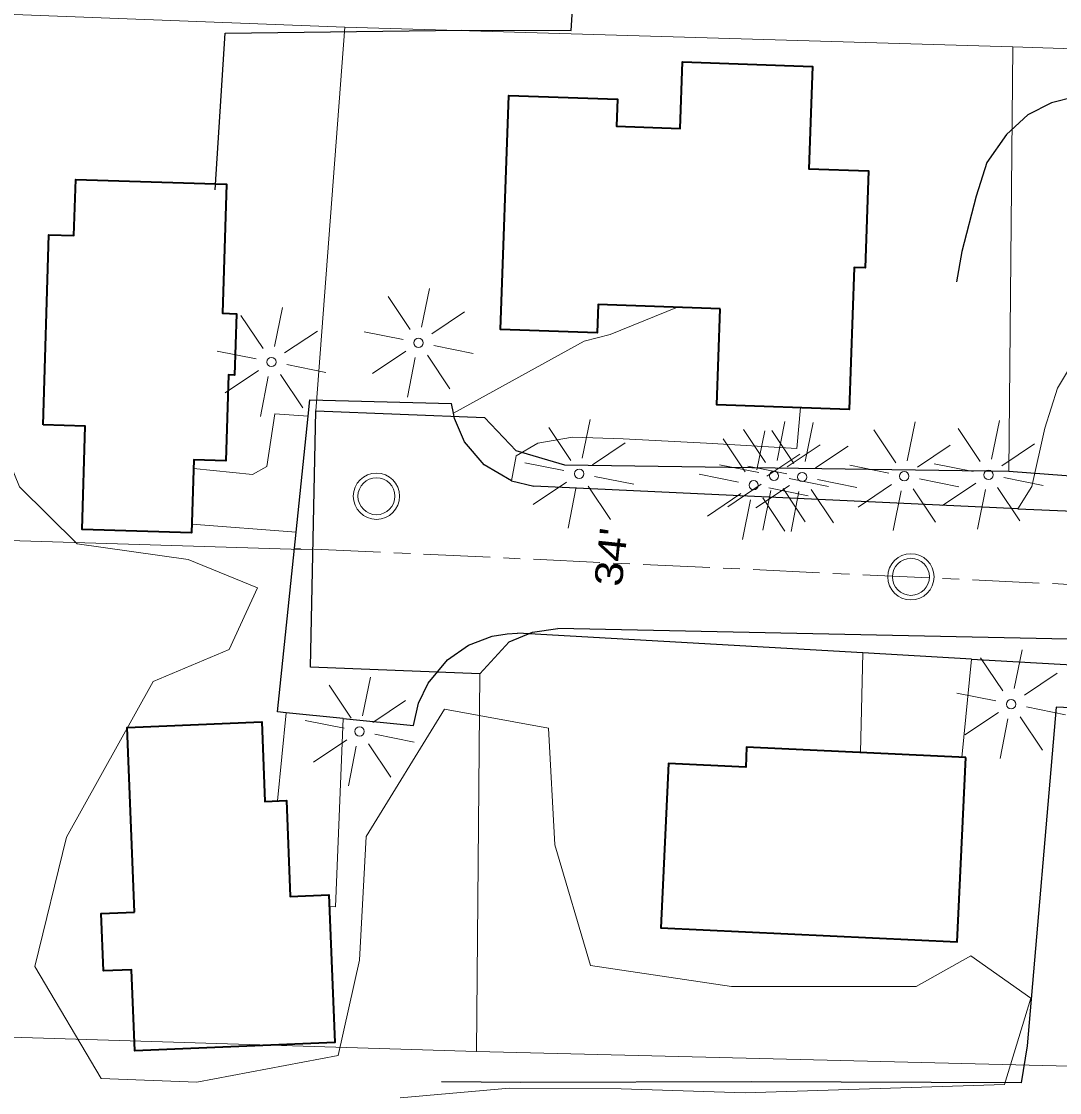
# Model space of a CAD drawing. Extents: x -861682 to -858969, y -1797841 to -1795153.
# Drawn here: x -859366.1 to -859141.7, y -1797575.9 to -1797344.4 of the extents above; entities that cross this region are included whole.
import ezdxf

# ---------------------------------------------------------------- set-up
doc = ezdxf.new("R2010")
doc.units = 0
doc.header["$LTSCALE"] = 2.4
doc.linetypes.add('LONG_DASH_SHORT_DASH', pattern=[9.9, 6, -1.2, 1.5, -1.2])
for name, color, linetype, lineweight in [('10', 7, 'Continuous', 25), ('11', 7, 'Continuous', 13), ('12', 7, 'Continuous', 35), ('14', 7, 'Continuous', 25), ('17', 7, 'Continuous', 13), ('18', 7, 'Continuous', 13), ('30', 7, 'Continuous', 13), ('32', 7, 'LONG_DASH_SHORT_DASH', 13), ('36', 7, 'Continuous', 13), ('42', 7, 'Continuous', 25)]:
    doc.layers.add(name, color=color, linetype=linetype, lineweight=lineweight)
doc.layers.add('43', color=7, linetype='Continuous')

msp = doc.modelspace()

# ---------------------------------------------------------------- linework, layer by layer
at = {"layer": '10'}
for p, q in [((-859272.713, -1797429.031), (-859273.117, -1797426.947)), ((-859260.141, -1797443.689), (-859255.295, -1797444.87)), ((-859150.644, -1797449.718), (-859255.295, -1797444.87)), ((-859150.644, -1797449.718), (-859138.672, -1797450.273)), ((-859184.173, -1797480.878), (-859258.846, -1797476.64)), ((-859160.676, -1797482.211), (-859184.173, -1797480.878)), ((-859160.676, -1797482.211), (-859048.845, -1797488.56)), ((-859296.507, -1797495.075), (-859308.828, -1797493.835)), ((-859296.507, -1797495.075), (-859281.36, -1797496.6))]:
    msp.add_line(p, q, dxfattribs=at)
for points in [[(-859304.087, -1797429.705), (-859303.724, -1797426.21), (-859273.117, -1797426.947)], [(-859308.828, -1797493.835), (-859310.746, -1797493.643), (-859306.695, -1797454.749), (-859304.087, -1797429.705)], [(-859260.141, -1797443.689), (-859266.026, -1797440.232), (-859270.305, -1797435.23), (-859272.489, -1797430.189), (-859272.713, -1797429.031)], [(-859281.36, -1797496.6), (-859280.237, -1797491.739), (-859278.186, -1797487.423), (-859273.961, -1797482.367), (-859269.444, -1797479.236), (-859264.304, -1797477.288), (-859261.047, -1797476.739), (-859258.846, -1797476.64)]]:
    msp.add_lwpolyline(points, dxfattribs=at)
at = {"layer": '11'}
for p, q in [((-859329.263, -1797453.014), (-859306.695, -1797454.749)), ((-859184.673, -1797502.437), (-859184.173, -1797480.878)), ((-859162.776, -1797503.462), (-859160.676, -1797482.211)), ((-859310.751, -1797512.854), (-859308.828, -1797493.835))]:
    msp.add_line(p, q, dxfattribs=at)
for points in [[(-859224.281, -1797406.168), (-859238.796, -1797412.061), (-859244.429, -1797413.499), (-859272.713, -1797429.031)], [(-859119.67, -1797415.266), (-859128.165, -1797415.055), (-859133.683, -1797415.671), (-859139.516, -1797419.326), (-859142.077, -1797423.661), (-859144.873, -1797432.314), (-859147.655, -1797444.888), (-859150.644, -1797449.718)], [(-859328.891, -1797440.981), (-859316.171, -1797442.278), (-859313.072, -1797440.589), (-859311.287, -1797429.197), (-859304.087, -1797429.705)], [(-859197.681, -1797427.858), (-859198.449, -1797436.724), (-859217.97, -1797435.521), (-859236.011, -1797434.6), (-859246.95, -1797434.245), (-859254.455, -1797435.567), (-859259.146, -1797438.272), (-859260.141, -1797443.689)], [(-859299.517, -1797535.703), (-859298.164, -1797535.787), (-859296.507, -1797495.075)]]:
    msp.add_lwpolyline(points, dxfattribs=at)
at = {"layer": '12'}
for points in [[(-859215.007, -1797406.494), (-859241.396, -1797405.569), (-859241.611, -1797411.69), (-859262.502, -1797410.956), (-859260.725, -1797360.393), (-859237.261, -1797361.218), (-859237.466, -1797367.049), (-859223.694, -1797367.533), (-859223.188, -1797353.142), (-859195.085, -1797354.13), (-859195.861, -1797376.217), (-859182.964, -1797376.67), (-859183.701, -1797397.655), (-859186.039, -1797397.573), (-859187.114, -1797428.229), (-859215.734, -1797427.225)], [(-859361.397, -1797431.566), (-859360.141, -1797390.509), (-859354.74, -1797390.674), (-859354.369, -1797378.534), (-859321.796, -1797379.529), (-859322.65, -1797407.475), (-859319.598, -1797407.568), (-859320.002, -1797420.812), (-859321.363, -1797420.77), (-859321.936, -1797439.351), (-859328.835, -1797439.138), (-859329.323, -1797454.953), (-859352.977, -1797454.223), (-859352.287, -1797431.847)], [(-859341.634, -1797536.908), (-859343.252, -1797496.981), (-859314.147, -1797495.802), (-859313.452, -1797512.964), (-859308.808, -1797512.776), (-859307.969, -1797533.503), (-859299.62, -1797533.165), (-859298.326, -1797565.121), (-859341.59, -1797566.873), (-859342.299, -1797549.359), (-859348.373, -1797549.605), (-859348.876, -1797537.202)], [(-859161.913, -1797503.503), (-859209.314, -1797501.284), (-859209.514, -1797505.548), (-859226.226, -1797504.764), (-859227.895, -1797540.335), (-859163.783, -1797543.344)]]:
    msp.add_lwpolyline(points, close=True, dxfattribs=at)
at = {"layer": '14'}
for points in [[(-859324.216, -1797380.81), (-859322.064, -1797346.914), (-859270.916, -1797346.242), (-859247.218, -1797346.364), (-859243.314, -1797283.008)], [(-859033.708, -1797365.447), (-859106.737, -1797361.329), (-859106.769, -1797356.675), (-859124.551, -1797356.727), (-859128.899, -1797356.969), (-859130.59, -1797360.624), (-859138.271, -1797360.661), (-859143.419, -1797362), (-859148.483, -1797364.556), (-859153.142, -1797368.793), (-859157.373, -1797374.905), (-859159.7, -1797382.153), (-859162.796, -1797394.134), (-859163.901, -1797400.693)], [(-859064.385, -1797496.166), (-859142.416, -1797492.569), (-859148.648, -1797565.786)], [(-859148.648, -1797565.786), (-859149.97, -1797573.797), (-859208.328, -1797573.579), (-859258.108, -1797573.761), (-859275.303, -1797573.594)]]:
    msp.add_lwpolyline(points, dxfattribs=at)
at = {"layer": '17'}
for p, q in [((-859282.046, -1797410.954), (-859286.836, -1797403.826)), ((-859279.586, -1797410.494), (-859277.86, -1797402.094)), ((-859311.39, -1797414.638), (-859309.664, -1797406.238)), ((-859313.85, -1797415.098), (-859318.64, -1797407.97)), ((-859277.386, -1797411.894), (-859270.29, -1797407.154)), ((-859309.19, -1797416.038), (-859302.094, -1797411.298)), ((-859283.546, -1797413.154), (-859292.008, -1797411.48)), ((-859315.35, -1797417.298), (-859323.812, -1797415.624)), ((-859283.006, -1797415.654), (-859290.232, -1797420.51)), ((-859276.946, -1797414.414), (-859268.466, -1797416.138)), ((-859282.626, -1797425.614), (-859280.946, -1797417.014)), ((-859278.286, -1797416.554), (-859273.486, -1797423.768)), ((-859314.81, -1797419.798), (-859322.036, -1797424.654)), ((-859308.75, -1797418.558), (-859300.27, -1797420.282)), ((-859314.43, -1797429.758), (-859312.75, -1797421.158)), ((-859310.09, -1797420.698), (-859305.29, -1797427.912)), ((-859247.307, -1797439.253), (-859252.097, -1797432.125)), ((-859244.847, -1797438.793), (-859243.121, -1797430.393)), ((-859202.742, -1797439.253), (-859201.016, -1797430.853)), ((-859196.639, -1797439.501), (-859194.913, -1797431.101)), ((-859174.571, -1797439.331), (-859172.845, -1797430.931)), ((-859156.341, -1797439.033), (-859154.615, -1797430.633)), ((-859205.202, -1797439.713), (-859209.992, -1797432.585)), ((-859207.136, -1797441.276), (-859205.41, -1797432.876)), ((-859199.099, -1797439.961), (-859203.889, -1797432.833)), ((-859177.031, -1797439.791), (-859181.821, -1797432.663)), ((-859158.801, -1797439.493), (-859163.591, -1797432.365)), ((-859242.647, -1797440.193), (-859235.551, -1797435.453)), ((-859209.596, -1797441.736), (-859214.386, -1797434.608)), ((-859200.542, -1797440.653), (-859193.446, -1797435.913)), ((-859194.439, -1797440.901), (-859187.343, -1797436.161)), ((-859172.371, -1797440.731), (-859165.275, -1797435.991)), ((-859154.141, -1797440.433), (-859147.045, -1797435.693)), ((-859204.936, -1797442.676), (-859197.84, -1797437.936)), ((-859248.807, -1797441.453), (-859257.269, -1797439.779)), ((-859206.702, -1797441.913), (-859215.164, -1797440.239)), ((-859200.599, -1797442.161), (-859209.061, -1797440.487)), ((-859178.531, -1797441.991), (-859186.993, -1797440.317)), ((-859160.301, -1797441.693), (-859168.763, -1797440.019)), ((-859242.207, -1797442.713), (-859233.727, -1797444.437)), ((-859211.096, -1797443.936), (-859219.558, -1797442.262)), ((-859200.102, -1797443.173), (-859191.622, -1797444.897)), ((-859193.999, -1797443.421), (-859185.519, -1797445.145)), ((-859171.931, -1797443.251), (-859163.451, -1797444.975)), ((-859153.701, -1797442.953), (-859145.221, -1797444.677)), ((-859248.267, -1797443.953), (-859255.493, -1797448.809)), ((-859247.887, -1797453.913), (-859246.207, -1797445.313)), ((-859243.547, -1797444.853), (-859238.747, -1797452.067)), ((-859206.162, -1797444.413), (-859213.388, -1797449.269)), ((-859200.059, -1797444.661), (-859207.285, -1797449.517)), ((-859205.782, -1797454.373), (-859204.102, -1797445.773)), ((-859204.496, -1797445.196), (-859196.016, -1797446.92)), ((-859201.442, -1797445.313), (-859196.642, -1797452.527)), ((-859199.679, -1797454.621), (-859197.999, -1797446.021)), ((-859195.339, -1797445.561), (-859190.539, -1797452.775)), ((-859177.991, -1797444.491), (-859185.217, -1797449.347)), ((-859177.611, -1797454.451), (-859175.931, -1797445.851)), ((-859173.271, -1797445.391), (-859168.471, -1797452.605)), ((-859159.761, -1797444.193), (-859166.987, -1797449.049)), ((-859159.381, -1797454.153), (-859157.701, -1797445.553)), ((-859155.041, -1797445.093), (-859150.241, -1797452.307)), ((-859210.556, -1797446.436), (-859217.782, -1797451.292)), ((-859210.176, -1797456.396), (-859208.496, -1797447.796)), ((-859205.836, -1797447.336), (-859201.036, -1797454.55)), ((-859151.471, -1797488.603), (-859149.745, -1797480.203)), ((-859153.931, -1797489.063), (-859158.721, -1797481.935)), ((-859149.271, -1797490.003), (-859142.175, -1797485.263)), ((-859292.337, -1797494.496), (-859290.611, -1797486.096)), ((-859294.797, -1797494.956), (-859299.587, -1797487.828)), ((-859155.431, -1797491.263), (-859163.893, -1797489.589)), ((-859290.137, -1797495.896), (-859283.041, -1797491.156)), ((-859154.891, -1797493.763), (-859162.117, -1797498.619)), ((-859148.831, -1797492.523), (-859140.351, -1797494.247)), ((-859296.297, -1797497.156), (-859304.759, -1797495.482)), ((-859154.511, -1797503.723), (-859152.831, -1797495.123)), ((-859150.171, -1797494.663), (-859145.371, -1797501.877)), ((-859289.697, -1797498.416), (-859281.217, -1797500.14)), ((-859295.757, -1797499.656), (-859302.983, -1797504.512)), ((-859295.377, -1797509.616), (-859293.697, -1797501.016)), ((-859291.037, -1797500.556), (-859286.237, -1797507.77))]:
    msp.add_line(p, q, dxfattribs=at)
for centre in [(-859280.246, -1797413.854), (-859312.05, -1797417.998), (-859245.507, -1797442.153), (-859157.001, -1797442.393), (-859207.796, -1797444.636), (-859203.402, -1797442.613), (-859197.299, -1797442.861), (-859175.231, -1797442.691), (-859152.131, -1797491.963), (-859292.997, -1797497.856)]:
    msp.add_circle(centre, 1, dxfattribs=at)
at = {"layer": '18'}
for points in [[(-859321.198, -1797480.165), (-859315.084, -1797466.839), (-859330.062, -1797460.69), (-859354.069, -1797457.299), (-859366.5, -1797444.967), (-859377.992, -1797416.89), (-859382.553, -1797384.396), (-859376.512, -1797338.569), (-859372.98, -1797327.794), (-859379.207, -1797311.989), (-859373.138, -1797294.17), (-859367.781, -1797289.434), (-859351.198, -1797287.652), (-859336.008, -1797286.23), (-859324.583, -1797275.591), (-859283.802, -1797261.154), (-859288.607, -1797254.326), (-859288.751, -1797241.158), (-859294.072, -1797207.025), (-859313.613, -1797209.261), (-859338.479, -1797220.856), (-859378.264, -1797219.647), (-859385.245, -1797201.598), (-859341.309, -1797133.89)], [(-859284.218, -1797577.042), (-859260.542, -1797574.932), (-859236.433, -1797575.112), (-859209.628, -1797575.999), (-859153.532, -1797574.134), (-859147.859, -1797555.494), (-859160.87, -1797546.377), (-859172.686, -1797553.009), (-859212.577, -1797553.004), (-859243.043, -1797548.45), (-859250.804, -1797522.387), (-859252.149, -1797497.165), (-859274.645, -1797493.038), (-859291.54, -1797520.578), (-859292.994, -1797547.284), (-859297.64, -1797567.867), (-859328.17, -1797573.665), (-859348.895, -1797572.865), (-859363.207, -1797548.661), (-859356.324, -1797520.728), (-859337.618, -1797487.055), (-859321.198, -1797480.165)]]:
    msp.add_lwpolyline(points, dxfattribs=at)
at = {"layer": '30'}
for p, q in [((-859302.428, -1797428.532), (-859296.184, -1797345.606)), ((-859151.786, -1797349.906), (-859296.184, -1797345.606)), ((-859152.641, -1797441.698), (-859151.786, -1797349.906)), ((-859024.68, -1797354.059), (-859151.786, -1797349.906)), ((-859417.416, -1797455.055), (-859303.062, -1797458.572)), ((-859267.682, -1797567.05), (-859126.119, -1797570.529))]:
    msp.add_line(p, q, dxfattribs=at)
for points in [[(-859830.296, -1797327.703), (-859414.772, -1797341.094), (-859296.184, -1797345.606)], [(-859414.772, -1797341.094), (-859419.905, -1797562.367), (-859267.682, -1797567.05), (-859267.003, -1797485.394)]]:
    msp.add_lwpolyline(points, dxfattribs=at)
at = {"layer": '32'}
msp.add_line((-859027.411, -1797471.328), (-859307.057, -1797458.229), dxfattribs=at)
at = {"layer": '36'}
for centre, radius in [((-859289.345, -1797447.008), 5), ((-859289.345, -1797447.008), 4), ((-859173.785, -1797464.432), 5), ((-859173.785, -1797464.432), 4)]:
    msp.add_circle(centre, radius, dxfattribs=at)
at = {"layer": '42'}
for p, q in [((-859302.428, -1797428.532), (-859265.984, -1797429.985)), ((-859152.641, -1797441.698), (-859248.581, -1797440.332)), ((-859026.94, -1797451.109), (-859152.641, -1797441.698)), ((-859125.863, -1797478.159), (-859250.133, -1797475.623))]:
    msp.add_line(p, q, dxfattribs=at)
for points in [[(-859267.003, -1797485.394), (-859303.598, -1797483.928), (-859302.428, -1797428.532)], [(-859248.581, -1797440.332), (-859259.147, -1797437.205), (-859265.984, -1797429.985)], [(-859267.003, -1797485.394), (-859260.669, -1797478.504), (-859255.585, -1797476.414), (-859250.133, -1797475.623)]]:
    msp.add_lwpolyline(points, dxfattribs=at)

# ---------------------------------------------------------------- texts
at = {"layer": '43', "width": 1.2}
msp.add_text("34'", height=6, rotation=83.991, dxfattribs=at).set_placement((-859236.326, -1797466.711))

doc.saveas('drawing.dxf')
